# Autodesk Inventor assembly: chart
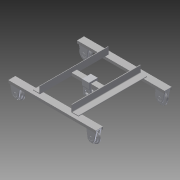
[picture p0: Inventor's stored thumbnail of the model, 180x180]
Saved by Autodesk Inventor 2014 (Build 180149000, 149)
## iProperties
Created: 2009-11
Part Number: chart
Document SubType Name: Assembly
Designer: pokornp
Mass: 486181 g
Surface Area: 105082 cm^2
Volume: 115860 cm^3
Density: 4.19629 g/cm^3
_SolveAssemblyDoc: Frame Generator Solve Assembly
_Version: 15.0.0
Author: pokornp
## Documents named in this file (5)
- C:\Users\iTools\Desktop\tutorial files\Frame Analysis 1\chart.iam
- C:\Users\iTools\Desktop\tutorial files\Frame Analysis 1\frame.ipt
- C:\Users\iTools\Desktop\tutorial files\Frame Analysis 1\side1.iam
- C:\Users\iTools\Desktop\tutorial files\Frame Analysis 1\Assembly2\Frame\Frame0001.iam
- C:\Users\iTools\Desktop\tutorial files\Frame Analysis 1\Part12.ipt
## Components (5 placed, 4 different names)
1. frame:1
2. side1:1 [sub-assembly] — Flush:6, Mate:6, Flush:8, Flush:9, Flush:10
3. side1:2 [sub-assembly] — Flush:6, Mate:6, Mate:7, Flush:9
4. Frame0001:1 [sub-assembly] — Flush:4, Mate:4, Mate:5, Flush:5, Mate:7, Flush:8, Flush:10
5. Part12:1 — Flush:4, Mate:4, Mate:5, Flush:5
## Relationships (10: Flush 6, Mate 4)
- Flush:4: Frame0001:1 ↔ Part12:1
- Mate:4: Frame0001:1 ↔ Part12:1
- Mate:5: Frame0001:1 ↔ Part12:1
- Flush:5: Frame0001:1 ↔ Part12:1
- Flush:6: side1:1 ↔ side1:2
- Mate:6: side1:1 ↔ side1:2
- Mate:7: side1:2 ↔ Frame0001:1
- Flush:8: side1:1 ↔ Frame0001:1
- Flush:9: side1:1 ↔ side1:2
- Flush:10: side1:1 ↔ Frame0001:1
